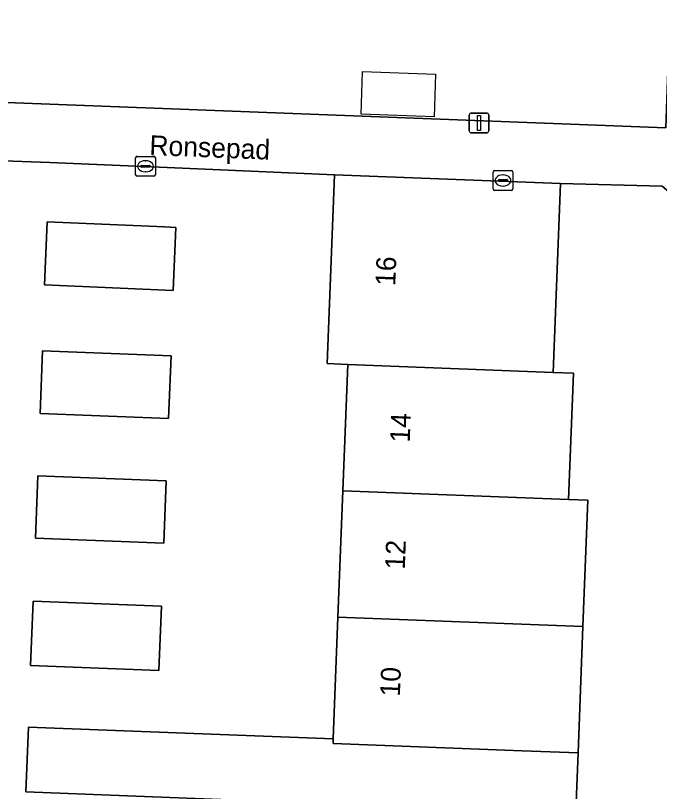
# Model space of a CAD drawing. Extents: x 160732 to 162107, y 387428 to 388479.
# Drawn here: x 161124.89 to 161157.41, y 387650.15 to 387689.33 of the extents above; entities that cross this region are included whole.
import ezdxf

# ---------------------------------------------------------------- set-up
doc = ezdxf.new("R2010")
doc.units = 0
for name, color, linetype in [('IMGEO_Erf', 7, 'Continuous'), ('IMGEO_Kolk', 7, 'Continuous'), ('IMGEO_Lichtmast', 7, 'Continuous'), ('IMGEO_Openbare_ruimte_label', 7, 'Continuous'), ('IMGEO_Pand', 7, 'Continuous'), ('IMGEO_Pand_nummerreeks', 7, 'Continuous'), ('IMGEO_Pand_vergunning_verleend', 7, 'Continuous'), ('IMGEO_Voetpad_open', 7, 'Continuous')]:
    doc.layers.add(name, color=color, linetype=linetype)

msp = doc.modelspace()

# ---------------------------------------------------------------- linework, layer by layer
at = {"layer": 'IMGEO_Erf'}
for points in [[(161115.604, 387711.866), (161115.535, 387710.66), (161115.689, 387710.643), (161115.059, 387694.991), (161114.651, 387685.302), (161122.654, 387684.997), (161157.729, 387683.661), (161158.641, 387709.529)], [(161141.168, 387658.955), (161141.416, 387665.334), (161141.664, 387671.712), (161140.626, 387671.752), (161140.997, 387681.285), (161132.542, 387681.663), (161126.614, 387681.9), (161124.277, 387681.994)], [(161159.959, 387670.036), (161158.584, 387670.098), (161158.688, 387671.93), (161159.084, 387678.892), (161158.458, 387679.941), (161157.536, 387680.714), (161152.408, 387680.842), (161152.037, 387671.309), (161153.057, 387671.269), (161152.809, 387664.891), (161153.788, 387664.853), (161153.54, 387658.474), (161153.292, 387652.096), (161153.046, 387645.765), (161150.218, 387645.875), (161150.216, 387645.828), (161152.873, 387645.725), (161152.625, 387639.347), (161149.968, 387639.45), (161149.72, 387633.072), (161149.469, 387626.618), (161158.888, 387626.423)], [(161122.246, 387627.904), (161139.928, 387627.069), (161140.176, 387633.443), (161140.424, 387639.821), (161140.672, 387646.199), (161140.801, 387649.524), (161125.41, 387650.122), (161125.538, 387653.397), (161140.929, 387652.799), (161141.168, 387658.955)]]:
    msp.add_lwpolyline(points, dxfattribs=at)
for points in [[(161126.349, 387675.723), (161126.486, 387678.907), (161132.413, 387678.653), (161132.982, 387678.629), (161132.845, 387675.445)], [(161126.124, 387669.228), (161126.247, 387672.401), (161132.743, 387672.149), (161132.619, 387668.976)], [(161125.888, 387662.937), (161126.01, 387666.086), (161132.499, 387665.834), (161132.376, 387662.685)], [(161132.13, 387656.249), (161125.642, 387656.501), (161125.769, 387659.758), (161132.256, 387659.506)]]:
    msp.add_lwpolyline(points, close=True, dxfattribs=at)
at = {"layer": 'IMGEO_Kolk'}
for p, q in [((161130.949, 387681.293), (161130.949, 387682.145)), ((161131.024, 387682.219), (161131.876, 387682.219)), ((161131.95, 387682.145), (161131.95, 387681.293)), ((161131.208, 387681.713), (161131.208, 387681.725)), ((161131.646, 387681.676), (161131.248, 387681.676)), ((161131.251, 387681.762), (161131.649, 387681.762)), ((161131.437, 387681.999), (161131.462, 387681.999)), ((161131.692, 387681.725), (161131.692, 387681.713)), ((161131.46, 387681.439), (161131.435, 387681.439)), ((161149.003, 387680.574), (161149.003, 387681.426)), ((161149.078, 387681.5), (161149.93, 387681.5)), ((161149.491, 387681.28), (161149.516, 387681.28)), ((161150.004, 387681.426), (161150.004, 387680.574)), ((161131.876, 387681.219), (161131.024, 387681.219)), ((161149.262, 387680.994), (161149.262, 387681.006)), ((161149.7, 387680.957), (161149.302, 387680.957)), ((161149.305, 387681.043), (161149.703, 387681.043)), ((161149.746, 387681.006), (161149.746, 387680.994)), ((161149.93, 387680.5), (161149.078, 387680.5)), ((161149.514, 387680.72), (161149.489, 387680.72))]:
    msp.add_line(p, q, dxfattribs=at)
for points in [[(161130.949, 387681.293), (161130.949, 387682.145)], [(161131.024, 387682.219), (161131.876, 387682.219)], [(161131.95, 387682.145), (161131.95, 387681.293)], [(161149.003, 387680.574), (161149.003, 387681.426)], [(161149.078, 387681.5), (161149.93, 387681.5)], [(161150.004, 387681.426), (161150.004, 387680.574)], [(161131.876, 387681.219), (161131.024, 387681.219)], [(161149.93, 387680.5), (161149.078, 387680.5)]]:
    msp.add_lwpolyline(points, dxfattribs=at)
for centre, radius, start, end in [((161131.026, 387682.143), 0.0765, 91.552, 178.448), ((161131.026, 387682.143), 0.0765, 91.552, 178.448), ((161131.874, 387682.143), 0.0765, 1.552, 88.448), ((161131.874, 387682.143), 0.0765, 1.552, 88.448), ((161131.248, 387681.722), 0.0403, 85.8775, 175.7526), ((161131.245, 387681.712), 0.0366, 178.938, 274.7102), ((161131.649, 387681.719), 0.043, 264.8664, 352.4533), ((161131.653, 387681.724), 0.0386, 1.7309, 96.639), ((161131.026, 387681.295), 0.0765, 181.552, 268.448), ((161131.026, 387681.295), 0.0765, 181.552, 268.448), ((161131.874, 387681.295), 0.0765, 271.552, 358.448), ((161131.874, 387681.295), 0.0765, 271.552, 358.448), ((161149.08, 387681.424), 0.0765, 91.552, 178.448), ((161149.08, 387681.424), 0.0765, 91.552, 178.448), ((161149.928, 387681.424), 0.0765, 1.552, 88.448), ((161149.928, 387681.424), 0.0765, 1.552, 88.448), ((161149.302, 387681.003), 0.0403, 85.8775, 175.7526), ((161149.299, 387680.993), 0.0366, 178.938, 274.7102), ((161149.703, 387681), 0.043, 264.8664, 352.4533), ((161149.707, 387681.005), 0.0386, 1.7309, 96.639), ((161149.08, 387680.576), 0.0765, 181.552, 268.448), ((161149.08, 387680.576), 0.0765, 181.552, 268.448), ((161149.928, 387680.576), 0.0765, 271.552, 358.448), ((161149.928, 387680.576), 0.0765, 271.552, 358.448)]:
    msp.add_arc(centre, radius, start, end, dxfattribs=at)
for centre, major_axis, ratio, start_param, end_param in [((161131.436, 387681.719), (-0.387, 0.002), 0.722429, 4.712389, 7.853982), ((161131.461, 387681.719), (-0.39, 0.002), 0.717154, 1.570796, 4.712389), ((161149.49, 387681), (-0.387, 0.002), 0.722429, 4.712389, 7.853982), ((161149.515, 387681), (-0.39, 0.002), 0.717154, 1.570796, 4.712389)]:
    msp.add_ellipse(centre, major_axis=major_axis, ratio=ratio, start_param=start_param, end_param=end_param, dxfattribs=at)
at = {"layer": 'IMGEO_Lichtmast'}
for p, q in [((161147.898, 387684.406), (161148.688, 387684.406)), ((161148.688, 387684.406), (161147.898, 387684.406)), ((161147.798, 387683.506), (161147.798, 387684.306)), ((161147.798, 387684.306), (161147.798, 387683.506)), ((161148.788, 387684.306), (161148.788, 387683.506)), ((161148.788, 387683.506), (161148.788, 387684.306)), ((161148.688, 387683.406), (161147.898, 387683.406)), ((161147.898, 387683.406), (161148.688, 387683.406))]:
    msp.add_line(p, q, dxfattribs=at)
msp.add_lwpolyline([(161148.218, 387684.281), (161148.368, 387684.281), (161148.368, 387683.531), (161148.218, 387683.531), (161148.218, 387684.281)], dxfattribs=at)
for centre, start, end in [((161147.898, 387684.306), 90, 180), ((161147.898, 387684.306), 90, 180), ((161148.688, 387684.306), 0, 90), ((161148.688, 387684.306), 360, 90), ((161147.898, 387683.506), 180, 270), ((161147.898, 387683.506), 180, 270), ((161148.688, 387683.506), 270, 0), ((161148.688, 387683.506), 270, 0)]:
    msp.add_arc(centre, 0.1, start, end, dxfattribs=at)
at = {"layer": 'IMGEO_Pand'}
for points in [[(161140.997, 387681.285), (161140.626, 387671.752), (161141.664, 387671.712), (161152.037, 387671.309), (161152.408, 387680.842)], [(161132.413, 387678.653), (161126.486, 387678.907), (161126.349, 387675.723), (161132.845, 387675.445), (161132.982, 387678.629)], [(161132.743, 387672.149), (161126.247, 387672.401), (161126.124, 387669.228), (161132.619, 387668.976)], [(161152.809, 387664.891), (161153.057, 387671.269), (161152.037, 387671.309), (161141.664, 387671.712), (161141.416, 387665.334)], [(161132.499, 387665.834), (161126.01, 387666.086), (161125.888, 387662.937), (161132.376, 387662.685)], [(161141.416, 387665.334), (161141.168, 387658.955), (161153.54, 387658.474), (161153.788, 387664.853), (161152.809, 387664.891)], [(161132.256, 387659.506), (161125.769, 387659.758), (161125.642, 387656.501), (161132.13, 387656.249)], [(161140.92, 387652.577), (161150.464, 387652.206), (161153.292, 387652.096), (161153.54, 387658.474), (161141.168, 387658.955), (161140.929, 387652.799)], [(161153.292, 387652.096), (161150.464, 387652.206), (161140.92, 387652.577), (161140.929, 387652.799), (161125.538, 387653.397), (161125.41, 387650.122), (161140.801, 387649.524), (161140.672, 387646.199), (161150.216, 387645.828), (161150.218, 387645.875), (161153.046, 387645.765)]]:
    msp.add_lwpolyline(points, close=True, dxfattribs=at)
at = {"layer": 'IMGEO_Pand_vergunning_verleend'}
msp.add_lwpolyline([(161142.416, 387686.498), (161146.095, 387686.371), (161146.02, 387684.215), (161142.338, 387684.342)], close=True, dxfattribs=at)
at = {"layer": 'IMGEO_Voetpad_open'}
for points in [[(161163.496, 387709.962), (161158.67, 387710.144), (161158.641, 387709.529), (161157.729, 387683.661), (161122.654, 387684.997), (161114.651, 387685.302), (161115.059, 387694.991), (161115.689, 387710.643), (161115.535, 387710.66), (161115.604, 387711.866)], [(161124.277, 387681.994), (161126.614, 387681.9), (161132.542, 387681.663), (161140.997, 387681.285), (161152.408, 387680.842), (161157.536, 387680.714), (161158.458, 387679.941), (161159.084, 387678.892), (161158.688, 387671.93), (161160.3, 387671.821), (161160.256, 387670.943), (161161.33, 387670.927), (161161.297, 387669.562)]]:
    msp.add_lwpolyline(points, dxfattribs=at)

# ---------------------------------------------------------------- texts
at = {"layer": 'IMGEO_Openbare_ruimte_label'}
msp.add_text('Ronsepad', height=1, rotation=357.8216, dxfattribs=at).set_placement((161131.633, 387682.284))
at = {"layer": 'IMGEO_Pand_nummerreeks'}
for s, rotation, p in [('16', 87.7739, (161144.061, 387675.66)), ('14', 87.773, (161144.793, 387667.757)), ('12', 87.773, (161144.543, 387661.339)), ('10', 87.773, (161144.294, 387654.929))]:
    msp.add_text(s, height=1, rotation=rotation, dxfattribs=at).set_placement(p)

doc.saveas('drawing.dxf')
